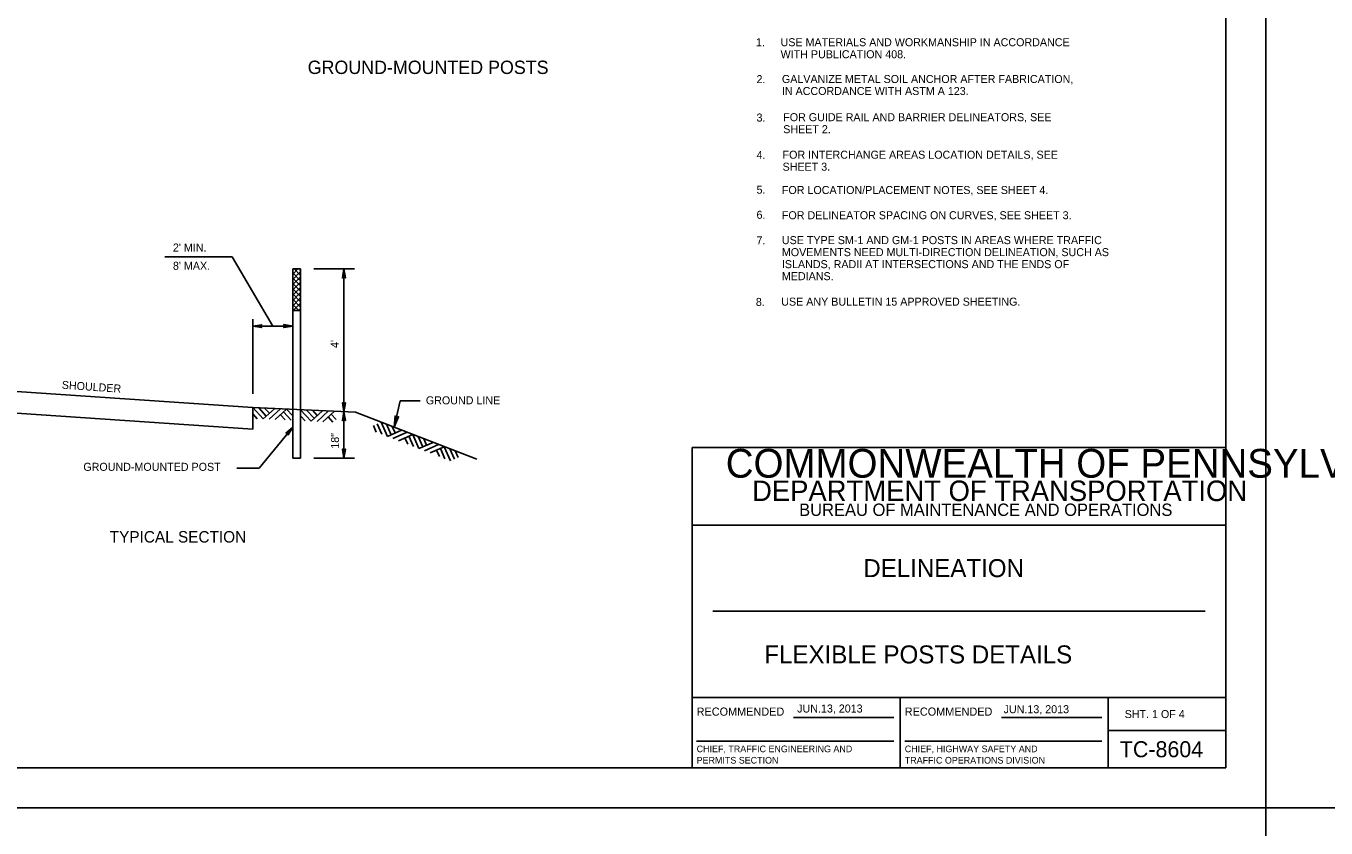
# Model space of a CAD drawing. Extents: x 640253 to 641999, y 298458 to 299646.
# Drawn here: x 640629.6 to 641116.9, y 299044.1 to 299344.6 of the extents above; entities that cross this region are included whole.
import ezdxf

# ---------------------------------------------------------------- set-up
doc = ezdxf.new("R2010")
doc.units = 0
for name, color, linetype in [('1', 7, 'Continuous'), ('2', 7, 'Continuous'), ('Level 1', 7, 'Continuous'), ('PLT-BNDY', 7, 'Continuous')]:
    doc.layers.add(name, color=color, linetype=linetype)

msp = doc.modelspace()

# ---------------------------------------------------------------- linework, layer by layer
at = {"layer": '1'}
for p, q in [((641079.31, 299066.63), (641079.31, 299630.63)), ((640879.31, 299066.63), (640879.31, 299186.63)), ((640879.31, 299186.63), (641079.31, 299186.63)), ((641079.31, 299157.63), (640879.31, 299157.63)), ((640887.06, 299125.31), (641071.56, 299125.31)), ((640879.31, 299093), (641079.31, 299093)), ((640957.31, 299093), (640957.31, 299066.63)), ((641035.19, 299066.63), (641035.19, 299093)), ((640917.24, 299085.57), (640954.87, 299085.57)), ((640995.24, 299085.57), (641032.87, 299085.57)), ((641035.19, 299080.63), (641079.31, 299080.63)), ((641079.31, 299066.63), (640293.31, 299066.63)), ((640293.31, 299066.63), (640879.31, 299066.63))]:
    msp.add_line(p, q, dxfattribs=at)
at = {"layer": '2'}
for p, q in [((640681.7, 299258.11), (640706.89, 299258.11)), ((640722.13, 299232.16), (640706.89, 299258.11)), ((640729.61, 299253.58), (640732.55, 299253.58)), ((640729.61, 299237.99), (640729.61, 299253.58)), ((640729.61, 299251.64), (640731.55, 299253.58)), ((640729.61, 299249.66), (640732.55, 299252.6)), ((640732.55, 299251.14), (640730.12, 299253.58)), ((640732.55, 299253.12), (640732.1, 299253.58)), ((640732.55, 299237.99), (640732.55, 299253.58)), ((640737.54, 299253.58), (640752.77, 299253.58)), ((640748.8, 299253.58), (640748.8, 299200.09)), ((640732.55, 299249.16), (640729.61, 299252.1)), ((640729.61, 299247.68), (640732.55, 299250.62)), ((640732.55, 299247.18), (640729.61, 299250.12)), ((640729.61, 299245.7), (640732.55, 299248.64)), ((640732.55, 299245.2), (640729.61, 299248.14)), ((640729.61, 299243.72), (640732.55, 299246.66)), ((640732.55, 299243.22), (640729.61, 299246.16)), ((640729.61, 299241.74), (640732.55, 299244.68)), ((640732.55, 299241.24), (640729.61, 299244.18)), ((640729.61, 299239.76), (640732.55, 299242.7)), ((640732.55, 299239.26), (640729.61, 299242.2)), ((640731.85, 299237.99), (640729.61, 299240.22)), ((640729.86, 299237.99), (640729.61, 299238.25)), ((640729.61, 299237.99), (640732.55, 299237.99)), ((640729.61, 299182.73), (640729.61, 299237.99)), ((640729.83, 299237.99), (640732.55, 299240.72)), ((640731.81, 299237.99), (640732.55, 299238.74)), ((640732.55, 299182.73), (640732.55, 299237.99)), ((640714.64, 299234.74), (640714.64, 299206.78)), ((640714.64, 299232.16), (640729.61, 299232.16)), ((640605.44, 299208.99), (640714.64, 299201.64)), ((640767.69, 299194.24), (640769.87, 299204.1)), ((640769.87, 299204.1), (640777.37, 299204.1)), ((640605.44, 299200.94), (640714.64, 299193.59)), ((640714.64, 299193.59), (640714.64, 299201.64)), ((640714.64, 299201.64), (640753.14, 299199.89)), ((640714.64, 299201.64), (640718.57, 299197.35)), ((640714.64, 299199.31), (640716.34, 299197.45)), ((640716.86, 299201.54), (640719.72, 299198.41)), ((640722.8, 299201.21), (640718.56, 299197.35)), ((640719.08, 299201.44), (640720.88, 299199.48)), ((640725.09, 299201.16), (640720.79, 299197.25)), ((640727.32, 299201.06), (640723.02, 299197.15)), ((640724.99, 299198.93), (640726.78, 299196.98)), ((640726.15, 299200), (640729.01, 299196.88)), ((640727.32, 299201.06), (640729.61, 299198.55)), ((640732.55, 299200.83), (640736.48, 299196.54)), ((640734.78, 299200.72), (640737.64, 299197.6)), ((640740.71, 299200.4), (640736.47, 299196.54)), ((640737, 299200.63), (640738.8, 299198.66)), ((640743, 299200.35), (640738.71, 299196.43)), ((640745.23, 299200.25), (640740.93, 299196.33)), ((640744.07, 299199.18), (640745.88, 299197.2)), ((640748.8, 299182.73), (640748.8, 299200.09)), ((640753.14, 299199.89), (640798.56, 299182.25)), ((640717.02, 299178.97), (640729.61, 299194.34)), ((640732.55, 299198.49), (640734.25, 299196.63)), ((640742.91, 299198.12), (640744.7, 299196.16)), ((640759.85, 299194.88), (640760.93, 299192.46)), ((640761.3, 299195.52), (640763.01, 299191.65)), ((640762.74, 299196.16), (640765.09, 299190.85)), ((640764.81, 299195.36), (640766.52, 299191.48)), ((640766.88, 299194.56), (640767.96, 299192.12)), ((640770.33, 299193.15), (640765.08, 299190.85)), ((640772.48, 299192.38), (640767.16, 299190.04)), ((640774.57, 299191.57), (640769.25, 299189.23)), ((640771.68, 299190.29), (640772.75, 299187.87)), ((640773.12, 299190.93), (640774.83, 299187.06)), ((640774.57, 299191.57), (640776.91, 299186.25)), ((640776.64, 299190.76), (640778.35, 299186.89)), ((640778.71, 299189.96), (640779.79, 299187.53)), ((640782.23, 299188.59), (640776.91, 299186.26)), ((640784.23, 299187.75), (640778.99, 299185.44)), ((640786.39, 299186.98), (640781.07, 299184.64)), ((640783.51, 299185.7), (640784.57, 299183.28)), ((640784.95, 299186.34), (640786.66, 299182.47)), ((640786.39, 299186.98), (640788.74, 299181.66)), ((640788.46, 299186.17), (640790.18, 299182.3)), ((640790.54, 299185.37), (640791.61, 299182.93)), ((640729.61, 299182.73), (640732.55, 299182.73)), ((640737.54, 299182.73), (640752.77, 299182.73)), ((640708.68, 299178.97), (640717.02, 299178.97))]:
    msp.add_line(p, q, dxfattribs=at)
for points in [[(640748.4, 299250.38), (640748.63, 299250.5), (640748.8, 299253.58), (640748.4, 299250.38), (640748.26, 299250.22), (640748.8, 299253.58), (640748.95, 299250.5), (640749.18, 299250.39), (640748.8, 299253.58), (640749.34, 299250.22), (640749.18, 299250.39)], [(640717.83, 299231.76), (640717.72, 299231.99), (640714.64, 299232.16), (640717.83, 299231.76), (640718, 299231.62), (640714.64, 299232.16), (640717.71, 299232.31), (640717.83, 299232.54), (640714.64, 299232.16), (640718, 299232.69), (640717.83, 299232.54)], [(640726.42, 299232.56), (640726.53, 299232.33), (640729.61, 299232.16), (640726.42, 299232.56), (640726.25, 299232.7), (640729.61, 299232.16), (640726.54, 299232.01), (640726.43, 299231.78), (640729.61, 299232.16), (640726.25, 299231.62), (640726.43, 299231.78)], [(640748.4, 299196.89), (640748.63, 299197.01), (640748.8, 299200.09), (640748.4, 299196.89), (640748.26, 299196.73), (640748.8, 299200.09), (640748.95, 299197.01), (640749.18, 299196.9), (640748.8, 299200.09), (640749.34, 299196.73), (640749.18, 299196.9)], [(640749.2, 299203.28), (640748.97, 299203.17), (640748.8, 299200.09), (640749.2, 299203.28), (640749.34, 299203.45), (640748.8, 299200.09), (640748.65, 299203.16), (640748.42, 299203.28), (640748.8, 299200.09), (640748.27, 299203.45), (640748.42, 299203.28)], [(640727.28, 299192.12), (640727.53, 299192.06), (640729.61, 299194.34), (640727.28, 299192.12), (640727.07, 299192.08), (640729.61, 299194.34), (640727.78, 299191.86), (640727.89, 299191.63), (640729.61, 299194.34), (640727.9, 299191.4), (640727.89, 299191.63)], [(640769.04, 299198.03), (640768.73, 299197.95), (640767.69, 299194.24), (640769.04, 299198.03), (640769.26, 299198.2), (640767.69, 299194.24), (640768.33, 299198.03), (640768.08, 299198.23), (640767.69, 299194.24), (640767.95, 299198.48), (640768.08, 299198.23)], [(640749.2, 299185.93), (640748.97, 299185.81), (640748.8, 299182.73), (640749.2, 299185.93), (640749.34, 299186.1), (640748.8, 299182.73), (640748.65, 299185.81), (640748.42, 299185.92), (640748.8, 299182.73), (640748.27, 299186.1), (640748.42, 299185.92)]]:
    msp.add_lwpolyline(points, dxfattribs=at)
at = {"layer": 'Level 1'}
for p, q in [((640880.99, 299076.68), (640954.87, 299076.68)), ((640958.99, 299076.68), (641032.87, 299076.68))]:
    msp.add_line(p, q, dxfattribs=at)
at = {"layer": 'PLT-BNDY'}
for points in [[(640253.31, 299645.63), (641094.31, 299645.63), (641094.31, 299051.63), (640253.31, 299051.63)], [(641094.31, 299645.63), (641935.31, 299645.63), (641935.31, 299051.63), (641094.31, 299051.63)], [(640253.31, 299051.63), (641094.31, 299051.63), (641094.31, 298457.63), (640253.31, 298457.63)], [(641094.31, 299051.63), (641935.31, 299051.63), (641935.31, 298457.63), (641094.31, 298457.63)]]:
    msp.add_lwpolyline(points, close=True, dxfattribs=at)

# ---------------------------------------------------------------- texts
at = {"layer": '1'}
for s, height, p in [('COMMONWEALTH OF PENNSYLVANIA', 10.7828, (640891.9, 299175.36)), ('DEPARTMENT OF TRANSPORTATION', 7.6837, (640901.76, 299166.61)), ('BUREAU OF MAINTENANCE AND OPERATIONS', 4.6253, (640919.41, 299161.04)), ('DELINEATION', 6.75, (640943.46, 299138.1)), ('FLEXIBLE POSTS DETAILS', 6.75, (640906.36, 299105.78)), ('RECOMMENDED', 3.048, (640880.99, 299086.2)), ('JUN.13, 2013', 3, (640918.66, 299087.39)), ('RECOMMENDED', 3.048, (640958.99, 299086.2)), ('JUN.13, 2013', 3, (640996.03, 299087.13)), ('SHT. 1 OF 4', 3, (641041.4, 299085.31)), ('TC-8604', 6, (641039.6, 299070.63))]:
    msp.add_text(s, height=height, dxfattribs=at).set_placement(p)
at = {"layer": '2'}
for s, height, p in [('USE MATERIALS AND WORKMANSHIP IN ACCORDANCE', 3, (640912.45, 299337)), ('1.', 3, (640903.23, 299337)), ('WITH PUBLICATION 408.', 3, (640912.45, 299332.5)), ('GROUND-MOUNTED POSTS', 5, (640735.22, 299326.6)), ('2.', 3, (640903.43, 299323.18)), ('GALVANIZE METAL SOIL ANCHOR AFTER FABRICATION,', 3, (640912.94, 299323.23)), ('IN ACCORDANCE WITH ASTM A 123.', 3, (640912.94, 299318.73)), ('3.', 3, (640903.43, 299308.78)), ('FOR GUIDE RAIL AND BARRIER DELINEATORS, SEE', 3, (640913.44, 299308.92)), ('SHEET 2.', 3, (640913.44, 299304.42)), ('4.', 3, (640903.43, 299294.77)), ('FOR INTERCHANGE AREAS LOCATION DETAILS, SEE', 3, (640913.19, 299294.86)), ('SHEET 3.', 3, (640913.19, 299290.36)), ('5.', 3, (640903.43, 299281.75)), ('FOR LOCATION/PLACEMENT NOTES, SEE SHEET 4.', 3, (640912.94, 299281.64)), ('6.', 3, (640903.43, 299272.36)), ('FOR DELINEATOR SPACING ON CURVES, SEE SHEET 3.', 3, (640912.94, 299272.19)), ("2' MIN.", 3, (640684.71, 299260.09)), ('7.', 3, (640903.43, 299262.79)), ('USE TYPE SM-1 AND GM-1 POSTS IN AREAS WHERE TRAFFIC', 3, (640912.94, 299262.86)), ('MOVEMENTS NEED MULTI-DIRECTION DELINEATION, SUCH AS', 3, (640912.94, 299258.36)), ("8' MAX.", 3, (640684.72, 299253.25)), ('MEDIANS.', 3, (640912.94, 299249.36)), ('ISLANDS, RADII AT INTERSECTIONS AND THE ENDS OF', 3, (640912.94, 299253.86)), ('USE ANY BULLETIN 15 APPROVED SHEETING.', 3, (640912.7, 299239.81)), ('GROUND LINE', 3, (640779.51, 299202.84)), ('GROUND-MOUNTED POST', 3, (640651.13, 299177.93)), ('TYPICAL SECTION', 4.3, (640661.04, 299151.06))]:
    msp.add_text(s, height=height, dxfattribs=at).set_placement(p)
for s, rotation, p in [('8.', 360, (640903.18, 299239.71)), ("4'", 90, (640746.83, 299223.95)), ('SHOULDER', 356.1494, (640642.99, 299208.68)), ('18"', 90, (640746.97, 299186.22))]:
    msp.add_text(s, height=3, rotation=rotation, dxfattribs=at).set_placement(p)
at = {"layer": 'Level 1'}
for s, p in [('CHIEF, TRAFFIC ENGINEERING AND', (640880.99, 299072.51)), ('CHIEF, HIGHWAY SAFETY AND', (640958.99, 299072.51)), ('PERMITS SECTION', (640880.99, 299068.26)), ('TRAFFIC OPERATIONS DIVISION', (640958.99, 299068.26))]:
    msp.add_text(s, height=2.5, dxfattribs=at).set_placement(p)

doc.saveas('drawing.dxf')
